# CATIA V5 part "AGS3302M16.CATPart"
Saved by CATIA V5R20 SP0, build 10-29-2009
Part number: AGS3302M16
Definition: NONE
Nomenclature: AGS3302M16
Source: Unknown
Description: AGS3302M16
Bounding box of the stored display mesh (mm): x -18.5 to 24, y -19.5 to 19.5, z -19.5 to 19.5
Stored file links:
  C:\Users\Utente\Desktop\IO LAVORO\3D X SITO CF\X SITO\PLASTICA\AGS\AGS3302M16.CATPart
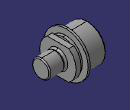
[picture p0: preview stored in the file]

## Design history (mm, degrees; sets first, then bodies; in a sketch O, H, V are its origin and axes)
Body1 "AGS3302M16" (main body)
  Solid1: solid without history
